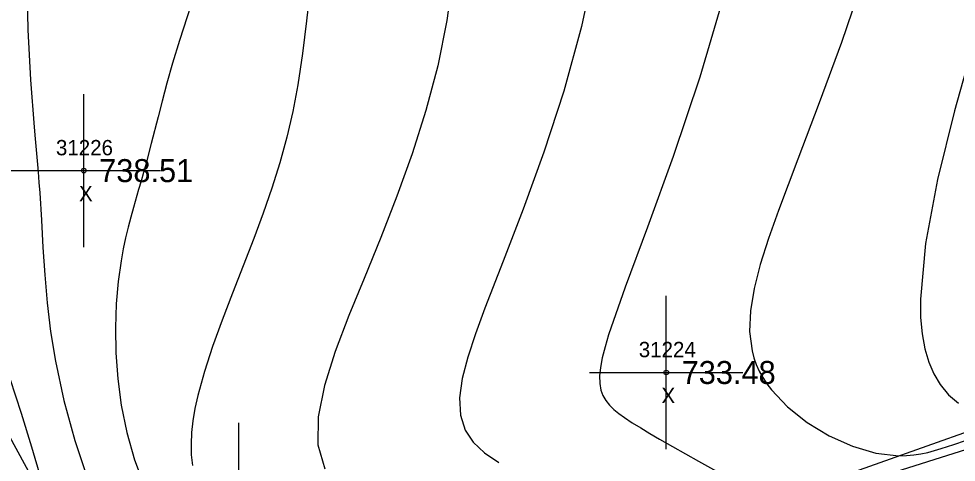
# Model space of a CAD drawing. Extents: x 1376587 to 1378239, y 1000335 to 1003031.
# Drawn here: x 1376884.3 to 1376945.5, y 1002511.2 to 1002540.2 of the extents above; entities that cross this region are included whole.
import ezdxf

# ---------------------------------------------------------------- set-up
doc = ezdxf.new("R2010")
doc.units = 0
for name, color, linetype in [('RD_DTM_BkLn1', 7, 'Continuous'), ('RD_DTM_Major1', 7, 'Continuous'), ('RD_DTM_Minor1', 7, 'Continuous'), ('RD_EX_Misc', 7, 'Continuous'), ('RD_EX_Misc_txCode', 7, 'Continuous'), ('RD_EX_Road', 7, 'Continuous'), ('RD_EX_TX_Misc_ELEV', 7, 'Continuous'), ('RD_SMD_Locator', 7, 'Continuous')]:
    doc.layers.add(name, color=color, linetype=linetype)

msp = doc.modelspace()

# ---------------------------------------------------------------- linework, layer by layer
at = {"layer": 'RD_DTM_BkLn1'}
msp.add_lwpolyline([(1376876.191, 1002526.786), (1376890.294, 1002500.826), (1376904.493, 1002499.417), (1376928.233, 1002506.872), (1376961.953, 1002518.841)], dxfattribs=at)
msp.add_spline([(1377003.447, 1002259.314), (1376973.187, 1002311.196), (1376942.719, 1002364.726), (1376914.248, 1002420.136), (1376886.108, 1002475.587), (1376860.058, 1002531.093), (1376835.652, 1002585.094), (1376813.12, 1002641.257), (1376777.121, 1002732.301)], degree=3, dxfattribs=at)
at = {"layer": 'RD_DTM_Major1'}
for points in [[(1376921.971, 1002544.094), (1376921.032, 1002539.686), (1376919.87, 1002535.47), (1376918.572, 1002531.484), (1376917.225, 1002527.768), (1376915.916, 1002524.361), (1376914.732, 1002521.304), (1376914.111, 1002519.626), (1376913.605, 1002518.091), (1376913.249, 1002516.697), (1376913.079, 1002515.441), (1376913.132, 1002514.324), (1376913.442, 1002513.342), (1376913.971, 1002512.558), (1376914.711, 1002511.862), (1376915.629, 1002511.227)], [(1376883.743, 1002516.715), (1376884.477, 1002514.452), (1376885.171, 1002512.246), (1376885.764, 1002510.189)]]:
    msp.add_lwpolyline(points, dxfattribs=at)
at = {"layer": 'RD_DTM_Minor1'}
for points in [[(1376897.025, 1002545.635), (1376894.803, 1002538.773), (1376894.361, 1002537.287), (1376893.99, 1002535.974), (1376893.677, 1002534.812), (1376893.411, 1002533.782), (1376892.97, 1002532.038), (1376892.796, 1002531.37), (1376892.628, 1002530.746), (1376892.465, 1002530.157), (1376892.304, 1002529.59), (1376892.144, 1002529.034), (1376891.807, 1002527.87), (1376891.631, 1002527.242), (1376891.458, 1002526.587), (1376891.293, 1002525.898), (1376891.139, 1002525.168), (1376890.999, 1002524.391), (1376890.815, 1002523.041), (1376890.689, 1002521.574), (1376890.634, 1002520.011), (1376890.663, 1002518.373), (1376890.787, 1002516.683), (1376891.019, 1002514.962), (1376891.383, 1002513.176), (1376891.883, 1002511.407), (1376892.526, 1002509.681)], [(1376912.728, 1002543.544), (1376912.254, 1002540.08), (1376911.647, 1002537.107), (1376910.879, 1002534.209), (1376909.982, 1002531.38), (1376908.99, 1002528.614), (1376907.935, 1002525.903), (1376906.852, 1002523.242), (1376905.861, 1002520.819), (1376904.97, 1002518.477), (1376904.272, 1002516.261), (1376903.864, 1002514.215), (1376903.841, 1002512.384), (1376904.298, 1002510.812)], [(1376939.403, 1002542.818), (1376937.978, 1002538.644), (1376936.522, 1002534.69), (1376935.124, 1002531.013), (1376933.868, 1002527.669), (1376933.22, 1002525.842), (1376932.681, 1002524.147), (1376932.277, 1002522.575), (1376932.036, 1002521.118), (1376931.982, 1002519.768), (1376932.144, 1002518.517), (1376932.267, 1002518.064), (1376932.426, 1002517.624), (1376932.62, 1002517.194), (1376932.85, 1002516.774), (1376933.116, 1002516.362), (1376933.418, 1002515.958), (1376934.465, 1002514.851), (1376935.738, 1002513.839), (1376937.17, 1002512.969), (1376938.689, 1002512.285), (1376940.229, 1002511.833), (1376941.719, 1002511.659), (1376942.21, 1002511.671), (1376942.687, 1002511.716), (1376943.151, 1002511.789), (1376943.604, 1002511.886), (1376944.046, 1002512.001), (1376944.477, 1002512.129), (1376945.298, 1002512.402), (1376946.056, 1002512.662)], [(1376884.866, 1002542.699), (1376884.916, 1002539.47), (1376885.102, 1002536.207), (1376885.346, 1002533.117), (1376885.411, 1002532.358), (1376885.534, 1002530.904), (1376885.591, 1002530.2), (1376885.645, 1002529.508), (1376885.694, 1002528.822), (1376885.805, 1002527.043), (1376885.908, 1002525.266), (1376886.026, 1002523.475), (1376886.184, 1002521.653), (1376886.407, 1002519.781), (1376886.718, 1002517.843), (1376887.268, 1002515.278), (1376887.979, 1002512.671), (1376888.828, 1002510.118)], [(1376903.35, 1002542.355), (1376903.087, 1002540.061), (1376902.834, 1002537.917), (1376902.539, 1002535.881), (1376902.207, 1002534.144), (1376901.806, 1002532.448), (1376901.344, 1002530.782), (1376900.826, 1002529.134), (1376900.261, 1002527.491), (1376899.654, 1002525.842), (1376898.967, 1002524.057), (1376898.271, 1002522.274), (1376897.597, 1002520.515), (1376896.974, 1002518.803), (1376896.433, 1002517.159), (1376896.006, 1002515.607), (1376895.821, 1002514.76), (1376895.686, 1002513.95), (1376895.6, 1002513.174), (1376895.565, 1002512.432), (1376895.582, 1002511.72), (1376895.653, 1002511.038)], [(1376930.386, 1002542.018), (1376928.74, 1002536.38), (1376927.001, 1002531.195), (1376925.326, 1002526.583), (1376923.872, 1002522.665), (1376922.797, 1002519.559), (1376922.561, 1002518.766), (1376922.382, 1002518.059), (1376922.261, 1002517.431), (1376922.203, 1002516.873), (1376922.211, 1002516.38), (1376922.286, 1002515.943), (1376922.417, 1002515.588), (1376922.603, 1002515.267), (1376922.842, 1002514.97), (1376923.129, 1002514.691), (1376923.462, 1002514.422), (1376923.837, 1002514.153), (1376924.336, 1002513.824), (1376924.885, 1002513.483), (1376925.482, 1002513.128), (1376926.122, 1002512.758), (1376928.653, 1002511.315), (1376929.833, 1002510.669)], [(1376946.636, 1002538.745), (1376945.349, 1002534.184), (1376944.248, 1002529.693), (1376943.464, 1002525.513), (1376943.125, 1002521.887), (1376943.139, 1002520.698), (1376943.234, 1002519.62), (1376943.41, 1002518.648), (1376943.665, 1002517.777), (1376943.997, 1002517.002), (1376944.405, 1002516.318), (1376944.96, 1002515.645), (1376945.606, 1002515.093)]]:
    msp.add_lwpolyline(points, dxfattribs=at)
at = {"layer": 'RD_EX_Misc'}
for p, q in [((1376888.574, 1002525.275), (1376888.574, 1002535.275)), ((1376883.574, 1002530.275), (1376893.574, 1002530.275)), ((1376926.555, 1002512.099), (1376926.555, 1002522.099)), ((1376921.555, 1002517.099), (1376931.555, 1002517.099)), ((1376898.685, 1002503.806), (1376898.685, 1002513.806))]:
    msp.add_line(p, q, dxfattribs=at)
at = {"layer": 'RD_EX_Road'}
msp.add_lwpolyline([(1376908.742, 1002499.002), (1376930.889, 1002507.274), (1376984.297, 1002524.174)], dxfattribs=at)
for points in [[(1377013.314, 1002264.907), (1376982.808, 1002315.683), (1376952.468, 1002370.341), (1376923.174, 1002424.32), (1376895.644, 1002480.03), (1376870.11, 1002535.049), (1376846.329, 1002588.864), (1376822.292, 1002645.031), (1376786.564, 1002736.458)], [(1376994.747, 1002253.913), (1376964.909, 1002306.463), (1376934.396, 1002359.987), (1376904.773, 1002415.485), (1376877.271, 1002471.511), (1376851.037, 1002526.893), (1376827.48, 1002581.62), (1376804.191, 1002637.821), (1376768.457, 1002728.838)]]:
    msp.add_spline(points, degree=3, dxfattribs=at)
at = {"layer": 'RD_SMD_Locator'}
for centre in [(1376888.574, 1002530.275), (1376926.555, 1002517.099)]:
    msp.add_circle(centre, 0.15, dxfattribs=at)

# ---------------------------------------------------------------- texts
at = {"layer": 'RD_EX_Misc_txCode'}
for s, p in [('31226', (1376886.755, 1002531.275)), ('X', (1376888.259, 1002528.275)), ('31224', (1376924.76, 1002518.099)), ('X', (1376926.24, 1002515.099))]:
    msp.add_text(s, height=1, dxfattribs=at).set_placement(p)
at = {"layer": 'RD_EX_TX_Misc_ELEV'}
for s, p in [('738.51', (1376889.574, 1002529.525)), ('733.48', (1376927.555, 1002516.349))]:
    msp.add_text(s, height=1.5, dxfattribs=at).set_placement(p)

doc.saveas('drawing.dxf')
